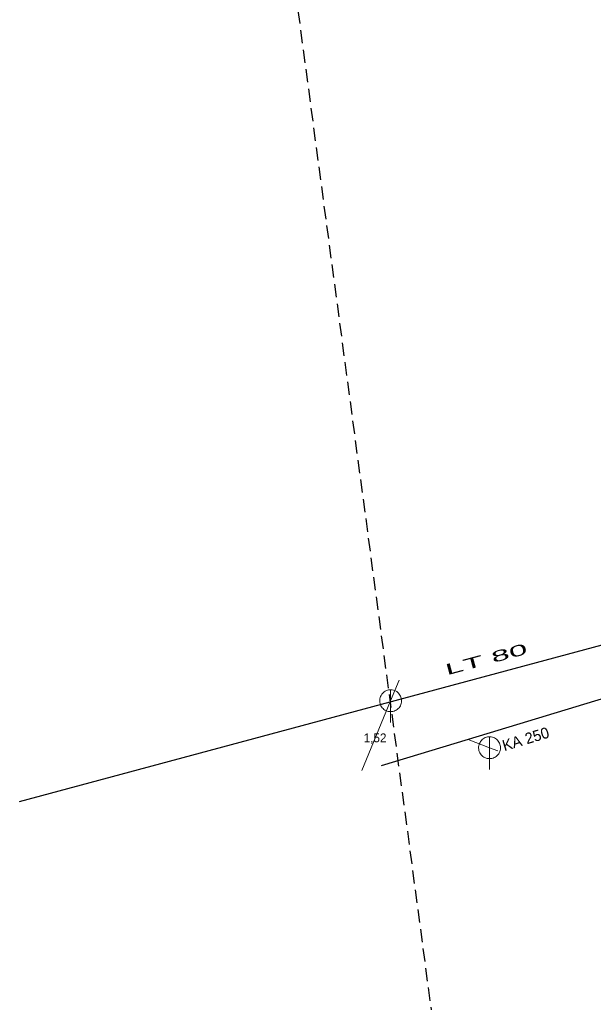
# Model space of a CAD drawing. Extents: x -682839 to -682312, y -994645 to -993949.
# Drawn here: x -682765.5 to -682713.1, y -994218.6 to -994128.9 of the extents above; entities that cross this region are included whole.
import ezdxf

# ---------------------------------------------------------------- set-up
doc = ezdxf.new("R2010")
doc.units = 0
doc.header["$LTSCALE"] = 0.4
doc.linetypes.add('MEDIUM_DASHED', pattern=[4.5, 3, -1.5])
doc.layers.add('1', color=7, linetype='Continuous')
for name, color, linetype, lineweight in [('11', 7, 'Continuous', 13), ('14', 7, 'Continuous', 25), ('17', 7, 'Continuous', 25), ('22', 7, 'Continuous', 13), ('63', 7, 'MEDIUM_DASHED', 25)]:
    doc.layers.add(name, color=color, linetype=linetype, lineweight=lineweight)

msp = doc.modelspace()

# ---------------------------------------------------------------- linework, layer by layer
at = {"layer": '11'}
for p, q in [((-682730.793, -994189.16), (-682731.576, -994191.045)), ((-682731.576, -994191.045), (-682734.219, -994197.41)), ((-682722.54, -994195.337), (-682724.48, -994194.579)), ((-682721.793, -994195.629), (-682722.54, -994195.337))]:
    msp.add_line(p, q, dxfattribs=at)
at = {"layer": '14'}
msp.add_lwpolyline([(-682705.35, -994188.789), (-682707.17, -994189.34), (-682711.949, -994190.789), (-682724.48, -994194.579), (-682732.44, -994196.989)], dxfattribs=at)
at = {"layer": '17'}
msp.add_line((-682765.462, -994200.262), (-682682.065, -994177.804), dxfattribs=at)
at = {"layer": '22'}
for p, q in [((-682731.576, -994193.045), (-682731.575, -994190.045)), ((-682722.54, -994197.337), (-682722.539, -994194.337))]:
    msp.add_line(p, q, dxfattribs=at)
for points in [[(-682730.576, -994191.045), (-682730.581, -994190.936), (-682730.599, -994190.828), (-682730.629, -994190.722), (-682730.669, -994190.621), (-682730.721, -994190.524), (-682730.783, -994190.434), (-682730.855, -994190.351), (-682730.935, -994190.277), (-682731.023, -994190.211), (-682731.117, -994190.156), (-682731.217, -994190.111), (-682731.322, -994190.078), (-682731.429, -994190.056), (-682731.538, -994190.046), (-682731.648, -994190.048), (-682731.756, -994190.062), (-682731.863, -994190.087), (-682731.966, -994190.124), (-682732.064, -994190.173), (-682732.156, -994190.231), (-682732.242, -994190.3), (-682732.319, -994190.377), (-682732.388, -994190.463), (-682732.447, -994190.555), (-682732.495, -994190.653), (-682732.532, -994190.756), (-682732.558, -994190.863), (-682732.572, -994190.971), (-682732.575, -994191.081), (-682732.565, -994191.19), (-682732.544, -994191.297), (-682732.51, -994191.401), (-682732.466, -994191.501), (-682732.411, -994191.596), (-682732.345, -994191.684), (-682732.271, -994191.764), (-682732.188, -994191.836), (-682732.098, -994191.898), (-682732.002, -994191.95), (-682731.9, -994191.991), (-682731.795, -994192.021), (-682731.687, -994192.039), (-682731.577, -994192.045), (-682731.468, -994192.039), (-682731.36, -994192.021), (-682731.255, -994191.992), (-682731.153, -994191.951), (-682731.056, -994191.899), (-682730.966, -994191.837), (-682730.883, -994191.766), (-682730.808, -994191.686), (-682730.743, -994191.598), (-682730.687, -994191.504), (-682730.643, -994191.404), (-682730.609, -994191.3), (-682730.587, -994191.192), (-682730.577, -994191.083)], [(-682721.54, -994195.337), (-682721.545, -994195.228), (-682721.563, -994195.12), (-682721.593, -994195.014), (-682721.633, -994194.913), (-682721.685, -994194.816), (-682721.747, -994194.726), (-682721.819, -994194.643), (-682721.899, -994194.569), (-682721.987, -994194.503), (-682722.081, -994194.448), (-682722.181, -994194.403), (-682722.286, -994194.37), (-682722.393, -994194.348), (-682722.502, -994194.338), (-682722.612, -994194.34), (-682722.72, -994194.354), (-682722.827, -994194.379), (-682722.93, -994194.416), (-682723.028, -994194.465), (-682723.12, -994194.523), (-682723.206, -994194.592), (-682723.283, -994194.669), (-682723.352, -994194.755), (-682723.411, -994194.847), (-682723.459, -994194.945), (-682723.496, -994195.048), (-682723.522, -994195.155), (-682723.536, -994195.263), (-682723.539, -994195.373), (-682723.529, -994195.482), (-682723.508, -994195.589), (-682723.474, -994195.693), (-682723.43, -994195.793), (-682723.375, -994195.888), (-682723.309, -994195.976), (-682723.235, -994196.056), (-682723.152, -994196.128), (-682723.062, -994196.19), (-682722.966, -994196.242), (-682722.864, -994196.283), (-682722.759, -994196.313), (-682722.651, -994196.331), (-682722.541, -994196.337), (-682722.432, -994196.331), (-682722.324, -994196.313), (-682722.219, -994196.284), (-682722.117, -994196.243), (-682722.02, -994196.191), (-682721.93, -994196.129), (-682721.847, -994196.058), (-682721.772, -994195.978), (-682721.707, -994195.89), (-682721.651, -994195.796), (-682721.607, -994195.696), (-682721.573, -994195.592), (-682721.551, -994195.484), (-682721.541, -994195.375)]]:
    msp.add_lwpolyline(points, close=True, dxfattribs=at)
at = {"layer": '63'}
msp.add_lwpolyline([(-682494.62, -994477.955), (-682564.4, -994570.065), (-682564.4, -994570.065), (-682684.423, -994544.944), (-682684.423, -994544.944), (-682751.412, -994042.525), (-682751.412, -994042.525), (-682670.466, -994042.525), (-682670.466, -994042.525)], close=True, dxfattribs=at)

# ---------------------------------------------------------------- texts
at = {"layer": '1', "width": 2.25}
msp.add_text('LT 80 ', height=1, rotation=15, dxfattribs=at).set_placement((-682726.432, -994188.73))
at = {"layer": '1'}
msp.add_text('1,52', height=0.8, dxfattribs=at).set_placement((-682734.039, -994194.837))
msp.add_text('KA 250', height=1, rotation=17, dxfattribs=at).set_placement((-682721.19, -994195.66))

doc.saveas('drawing.dxf')
